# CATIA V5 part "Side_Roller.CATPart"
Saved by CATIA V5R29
Part number: Side_Roller
Source: Unknown
Bounding box of the stored display mesh (mm): x -20 to 20, y -50 to 50, z -20 to 20
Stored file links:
  C:\가치같이\SmartFactory_BoxErectorConveyor\Side_Roller.CATPart
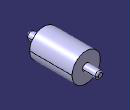
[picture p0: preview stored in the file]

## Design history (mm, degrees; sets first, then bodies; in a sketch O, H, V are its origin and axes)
Body1 (main body)
  Solid1 "PartBody": solid without history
